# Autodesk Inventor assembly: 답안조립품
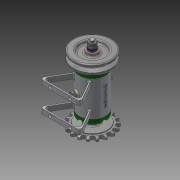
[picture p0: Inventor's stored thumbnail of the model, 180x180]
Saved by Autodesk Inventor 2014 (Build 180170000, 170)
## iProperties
Created: 2016-03
Part Number: 답안조립품
Document SubType Name: Assembly
Designer: 406-0077
Author: 406-0077
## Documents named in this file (15)
- C:\Users\406-0077\Desktop\460307V1015\답안조립품.iam
- C:\Users\406-0077\Desktop\460307V1015\1.본체.ipt
- C:\Users\406-0077\Desktop\460307V1015\커버.ipt
- C:\Users\406-0077\Desktop\460307V1015\베어링 15 x 32 x 9.ipt
- C:\Users\406-0077\Desktop\460307V1015\축.ipt
- C:\Users\406-0077\Desktop\460307V1015\키 3 x 3 x 12.ipt
- C:\Users\406-0077\Desktop\460307V1015\오일 실 15 25 7.ipt
- C:\Users\406-0077\Desktop\460307V1015\V벨트풀리.ipt
- C:\Users\406-0077\Desktop\460307V1015\스프로킷.ipt
- C:\Users\406-0077\Desktop\460307V1015\너트 M 8.ipt
- C:\Users\406-0077\Desktop\460307V1015\스프링와셔 8.ipt
- C:\Users\406-0077\Desktop\460307V1015\와셔 8x17.ipt
- C:\Users\406-0077\Desktop\460307V1015\니플 M 6 x 0.75.ipt
- C:\Users\406-0077\Desktop\460307V1015\볼트 M 6 x 8.ipt
- C:\Users\406-0077\Desktop\460307V1015\와셔 6x11.5.ipt
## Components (4 placed, 3 different names)
1. 1.본체:1
2. KS B 2023 6002 - 15 x 32 x 9:1
3. KS B 2023 6002 - 15 x 32 x 9:2
4. V벨트풀리:1 — 각도:3
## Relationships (1: Angle 1)
- 각도:3 [Angle]: V벨트풀리:1
